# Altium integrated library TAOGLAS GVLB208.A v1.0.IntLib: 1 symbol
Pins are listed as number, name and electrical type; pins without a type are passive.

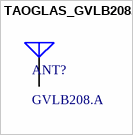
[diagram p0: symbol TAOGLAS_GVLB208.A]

## TAOGLAS_GVLB208.A
designator ANT?, comment GVLB208.A
GNSS L1/L5 Single Feed Stacked Patch 20*20*8mm; ComponentLibStatus: Created; MFG: Taoglas; Temp_High: +85C; Temp_Low: -40C
footprint TAOGLAS_GVLB208.A (GNSS L1/L5 Single Feed Stacked Patch 20*20*8mm)
pins: 1 RF FEED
